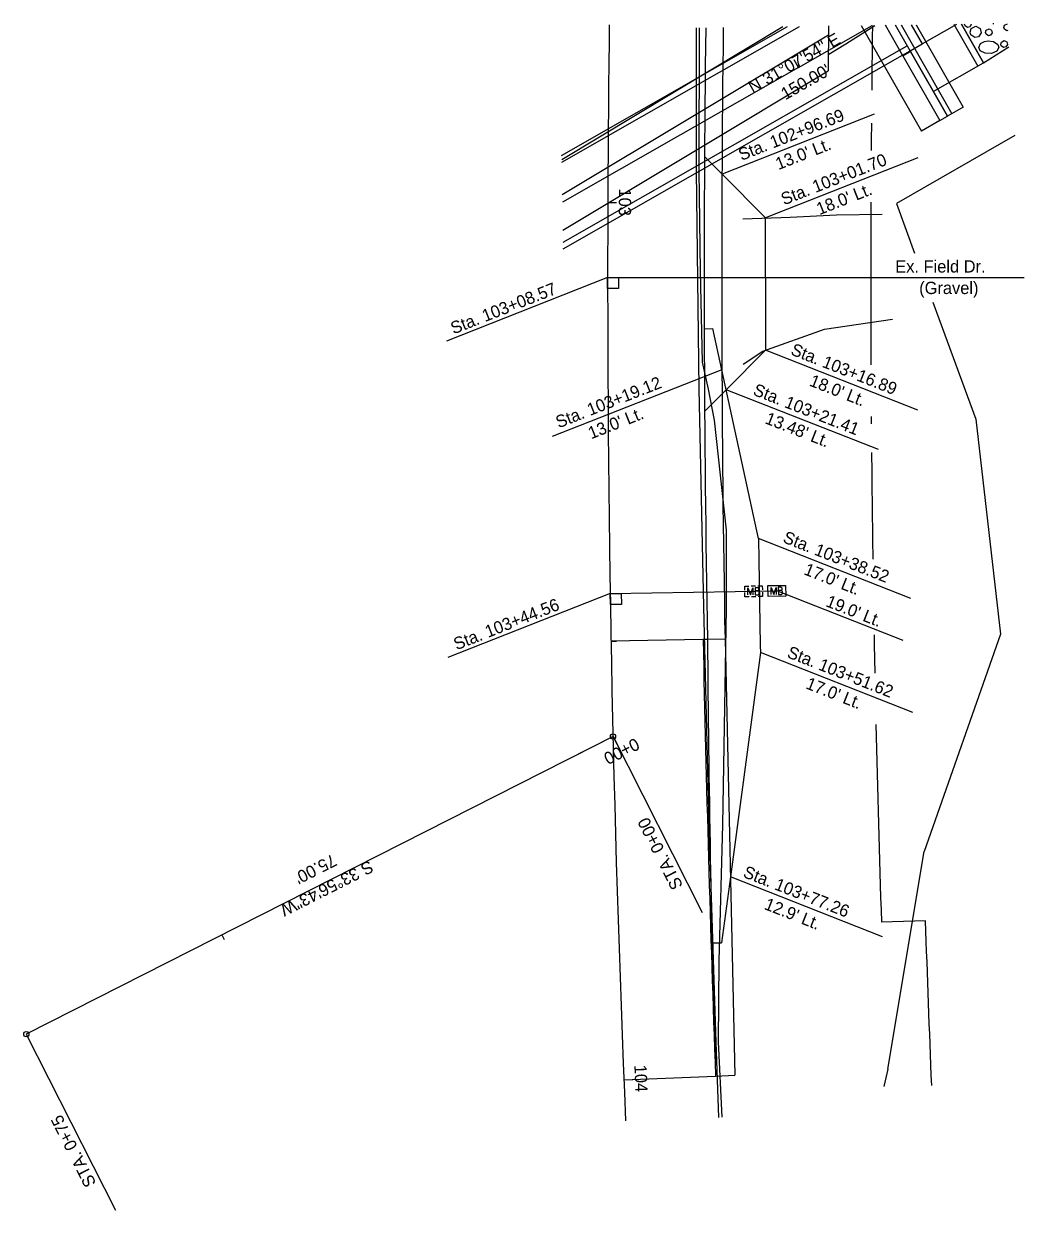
# Model space of a CAD drawing. Extents: x -189 to 370, y -316 to 69.
# Drawn here: x -189.4 to -75.3, y -65.9 to 69.3 of the extents above; entities that cross this region are included whole.
import ezdxf

# ---------------------------------------------------------------- set-up
doc = ezdxf.new("R2010")
doc.units = 0
for name, color, linetype in [('DR_P_Culvert', 7, 'Continuous'), ('DR_P_Erosion_Control', 7, 'Continuous'), ('DR_P_Paved_Gutter', 7, 'Continuous'), ('DR_X_Storm_Sewer', 7, 'Continuous'), ('DT_P_Slope_Break_Line', 7, 'Continuous'), ('GE_P_Alignment_100_Cardinal_Points', 7, 'Continuous'), ('GE_P_Alignment_100_Distances', 7, 'Continuous'), ('GE_P_Alignment_100_Stations', 7, 'Continuous'), ('GE_X_Alignment', 7, 'Continuous'), ('GE_X_Alignment_100_Stations', 7, 'Continuous'), ('HY_X_Water_Edge', 7, 'Continuous'), ('PF_P_Sta_Elev_Text', 7, 'Continuous'), ('PF_X_Text', 7, 'Continuous'), ('PV_P_Drive', 7, 'Continuous'), ('PV_P_Field_Drive', 7, 'Continuous'), ('PV_X_Driveway', 7, 'Continuous'), ('PV_X_EOP', 7, 'Continuous'), ('PV_X_Shoulder_Aggregate', 7, 'Continuous'), ('RD_X_Cells', 7, 'Continuous'), ('RW_P_Const_Limits', 7, 'Continuous'), ('RW_X_Esmt_SH', 7, 'Continuous'), ('ST_Text', 7, 'Continuous'), ('SV_X_Text', 7, 'Continuous'), ('TX_P_Misc', 7, 'Continuous'), ('XS_P_Finished_Grade', 7, 'Continuous')]:
    doc.layers.add(name, color=color, linetype=linetype)

msp = doc.modelspace()

# ---------------------------------------------------------------- linework, layer by layer
at = {"layer": 'DR_P_Culvert'}
for p, q in [((-128.04, 54.33), (-102.29, 69.02)), ((-128.03, 53.57), (-100.91, 69.04)), ((-127.86, 44.46), (-89.5, 66.34)), ((-89.5, 66.34), (-88.64, 66.84)), ((-89.17, 65.76), (-88.31, 66.26)), ((-127.85, 43.7), (-89.17, 65.76))]:
    msp.add_line(p, q, dxfattribs=at)
at = {"layer": 'DR_P_Erosion_Control'}
for p, q in [((-77.53, 69.17), (-77.22, 69.32)), ((-79.94, 64.88), (-77.04, 66.71))]:
    msp.add_line(p, q, dxfattribs=at)
for points in [[(-81.34, 69.31), (-81.33, 69.25), (-81.51, 68.98), (-81.77, 68.93), (-82.03, 69.11), (-82.09, 69.3)], [(-81.34, 68.8), (-80.82, 69.05), (-80.33, 68.82), (-80.19, 68.3), (-80.51, 67.85), (-80.93, 67.77), (-81.37, 68.07), (-81.47, 68.4), (-81.34, 68.8)], [(-78.76, 69.34), (-78.85, 69.33), (-78.87, 69.34)], [(-77.17, 68.58), (-77.29, 68.55), (-77.55, 68.73), (-77.61, 68.93), (-77.53, 69.17)], [(-79.63, 68.6), (-79.31, 68.75), (-79.02, 68.61), (-78.94, 68.3), (-79.13, 68.03), (-79.38, 67.98), (-79.65, 68.16), (-79.71, 68.36), (-79.63, 68.6)], [(-79.45, 67.39), (-78.78, 67.31), (-78.29, 66.98), (-78.18, 66.62), (-78.42, 66.21), (-79.04, 65.95), (-79.76, 65.98), (-80.3, 66.27), (-80.48, 66.65), (-80.27, 67.09), (-79.82, 67.33), (-79.42, 67.4)], [(-77.89, 67.26), (-77.57, 67.42), (-77.28, 67.28), (-77.2, 66.96), (-77.39, 66.7), (-77.64, 66.65), (-77.91, 66.82), (-77.97, 67.02), (-77.89, 67.26)]]:
    msp.add_lwpolyline(points, dxfattribs=at)
at = {"layer": 'DR_P_Paved_Gutter'}
for p, q in [((-86.93, 67.04), (-82.99, 69.29)), ((-82.46, 69.29), (-79.94, 64.89)), ((-85.66, 61.62), (-79.94, 64.89))]:
    msp.add_line(p, q, dxfattribs=at)
at = {"layer": 'DR_X_Storm_Sewer'}
for p, q in [((-128.03, 53.89), (-102.83, 69.01)), ((-97.6, 69.09), (-97.66, 63.96)), ((-97.61, 68.06), (-127.96, 49.85)), ((-127.89, 45.81), (-97.66, 63.96))]:
    msp.add_line(p, q, dxfattribs=at)
at = {"layer": 'DT_P_Slope_Break_Line'}
for p, q in [((-79.94, 64.88), (-82.46, 69.29)), ((-84.05, 58.8), (-88.26, 66.18))]:
    msp.add_line(p, q, dxfattribs=at)
at = {"layer": 'GE_P_Alignment_100_Cardinal_Points'}
for p, q in [((-122.18, -11.88), (-112, -31.94)), ((-122.18, -11.88), (-112, -31.94)), ((-189.07, -45.8), (-178.89, -65.87))]:
    msp.add_line(p, q, dxfattribs=at)
for centre in [(-122.18, -11.88), (-122.18, -11.88), (-189.07, -45.8)]:
    msp.add_circle(centre, 0.3, dxfattribs=at)
at = {"layer": 'GE_P_Alignment_100_Stations'}
for p, q in [((-101.04, 64.36), (-101.54, 65.23)), ((-122.18, -11.88), (-121.73, -12.77)), ((-122.18, -11.88), (-121.73, -12.77)), ((-166.77, -34.49), (-166.5, -35.03))]:
    msp.add_line(p, q, dxfattribs=at)
at = {"layer": 'GE_X_Alignment'}
for p, q in [((-101.04, 64.36), (-92.64, 69.15)), ((-101.04, 64.36), (-127.94, 49.01)), ((-122.18, -11.88), (-189.07, -45.8))]:
    msp.add_line(p, q, dxfattribs=at)
for start, end in [(179.26709, 179.78203), (179.78203, 182.44543)]:
    msp.add_arc((2128.84, 40.41), 2251.63, start, end, dxfattribs=at)
at = {"layer": 'GE_X_Alignment_100_Stations'}
for p, q in [((-122.77, 48.97), (-121.77, 48.97)), ((-122.77, 48.97), (-121.77, 48.97)), ((-122.4, -1.02), (-121.8, -1.01)), ((-122.4, -1.02), (-121.8, -1.01)), ((-120.93, -51), (-119.93, -50.96)), ((-120.93, -51), (-119.93, -50.96))]:
    msp.add_line(p, q, dxfattribs=at)
at = {"layer": 'HY_X_Water_Edge'}
msp.add_lwpolyline([(-97.58, 65.88), (-95.64, 67.07), (-92.31, 69.16)], dxfattribs=at)
at = {"layer": 'PF_P_Sta_Elev_Text'}
for p, q in [((-88.26, 66.18), (-88.31, 66.26)), ((-89.13, 65.69), (-89.17, 65.76))]:
    msp.add_line(p, q, dxfattribs=at)
msp.add_lwpolyline([(-89.17, 65.76), (-88.31, 66.26), (-88.26, 66.18), (-89.13, 65.69)], close=True, dxfattribs=at)
at = {"layer": 'PF_X_Text'}
for p, q in [((-93.88, 69.14), (-91.27, 64.56)), ((-89.17, 65.76), (-91.12, 69.17)), ((-88.31, 66.26), (-89.98, 69.19)), ((-89.31, 69.2), (-83.55, 59.09)), ((-88.17, 69.22), (-86.93, 67.04)), ((-87.6, 69.22), (-82.24, 59.83)), ((-83.32, 69.28), (-80.6, 64.51)), ((-88.31, 66.26), (-86.93, 67.04)), ((-89.13, 65.69), (-88.26, 66.18)), ((-89.13, 65.69), (-84.92, 58.31)), ((-88.26, 66.18), (-84.05, 58.8)), ((-91.27, 64.56), (-87.02, 57.11)), ((-82.24, 59.83), (-84.05, 58.8)), ((-84.92, 58.31), (-87.02, 57.11)), ((-84.92, 58.31), (-84.05, 58.8))]:
    msp.add_line(p, q, dxfattribs=at)
at = {"layer": 'PV_P_Drive'}
for p, q in [((-111.78, 34.59), (-110.78, 34.6)), ((-109.76, 29.91), (-110.78, 34.6)), ((-97.77, 34.58), (-97.78, 34.57)), ((-105.59, 10.68), (-109.76, 29.91)), ((-105.38, -2.31), (-108.8, -27.88)), ((-108.8, -27.88), (-109.81, -35.39)), ((-111.01, -35.41), (-109.81, -35.39))]:
    msp.add_line(p, q, dxfattribs=at)
msp.add_arc((2128.84, 40.41), 2234.63, 180.76225, 181.09547, dxfattribs=at)
at = {"layer": 'PV_P_Field_Drive'}
for p, q in [((-109.75, 52.22), (-111.74, 54.22)), ((-109.75, 52.22), (-104.79, 47.22)), ((-104.79, 40.41), (-104.79, 47.22)), ((-104.79, 40.41), (-104.79, 32.16)), ((-109.27, 27.64), (-104.79, 32.16)), ((-111.73, 25.16), (-109.27, 27.64))]:
    msp.add_line(p, q, dxfattribs=at)
at = {"layer": 'PV_X_Driveway'}
for points in [[(-107.37, 47.12), (-101.97, 47.32), (-96.68, 47.56), (-91.51, 47.64)], [(-107.35, 30.55), (-105.11, 32.04), (-98.05, 34.53), (-90.3, 35.66)]]:
    msp.add_lwpolyline(points, dxfattribs=at)
at = {"layer": 'PV_X_EOP'}
msp.add_lwpolyline([(-110.12, -55.28), (-110.43, -46.71), (-111.2, -21.94), (-111.81, 2.89), (-112.34, 27.73), (-112.65, 52.6), (-112.66, 68.88)], dxfattribs=at)
at = {"layer": 'PV_X_Shoulder_Aggregate'}
msp.add_lwpolyline([(-109.75, -55.26), (-110.14, -46.68), (-110.09, -37.44), (-109.65, -21.95), (-109.25, 2.7), (-109.24, 11.62), (-110.61, 24.17), (-111.29, 27.69), (-111.99, 30.79), (-112.2, 41.16), (-112.34, 52.6), (-112.31, 68.88)], dxfattribs=at)
at = {"layer": 'RD_X_Cells'}
for p, q in [((-106.42, 5.28), (-105.92, 5.29)), ((-106.39, 4.06), (-105.89, 4.07)), ((-106.15, 4.67), (-106.15, 4.67))]:
    msp.add_line(p, q, dxfattribs=at)
for points in [[(-107.15, 4.78), (-107.16, 5.26), (-106.68, 5.27)], [(-106.65, 4.05), (-107.14, 4.04), (-107.15, 4.53)], [(-106.79, 4.26), (-106.8, 5.06), (-106.5, 4.27), (-106.24, 5.07), (-106.22, 4.27)], [(-105.64, 4.72), (-105.61, 4.75), (-105.59, 4.77), (-105.58, 4.79), (-105.57, 4.8), (-105.56, 4.83), (-105.55, 4.84), (-105.54, 4.89), (-105.54, 4.91), (-105.54, 4.93), (-105.55, 4.97), (-105.56, 5), (-105.58, 5.03), (-105.61, 5.05), (-105.64, 5.06), (-105.65, 5.07), (-105.68, 5.08), (-105.99, 5.08), (-105.98, 4.28), (-105.63, 4.28), (-105.59, 4.31), (-105.55, 4.34), (-105.52, 4.39), (-105.5, 4.45), (-105.5, 4.5), (-105.5, 4.54), (-105.51, 4.58), (-105.54, 4.64), (-105.57, 4.67), (-105.64, 4.72), (-105.99, 4.71)], [(-105.66, 5.29), (-105.16, 5.3), (-105.15, 4.82)], [(-105.15, 4.57), (-105.14, 4.08), (-105.63, 4.07)]]:
    msp.add_lwpolyline(points, dxfattribs=at)
at = {"layer": 'RW_P_Const_Limits'}
for p, q in [((-76.37, 56.6), (-89.87, 48.85)), ((-89.87, 48.85), (-87.79, 43.21)), ((-85.73, 37.61), (-80.83, 24.28)), ((-80.83, 24.28), (-78.01, -0.21)), ((-78.01, -0.21), (-86.72, -24.98)), ((-90.84, -49.78), (-86.72, -24.98)), ((-90.84, -49.78), (-91.32, -51.78))]:
    msp.add_line(p, q, dxfattribs=at)
at = {"layer": 'RW_X_Esmt_SH'}
msp.add_line((-86.57, -32.88), (-91.57, -33.04), dxfattribs=at)
for radius, start, end in [(2221.63, 179.25863, 179.44925), (2221.63, 179.54618, 179.6263), (2221.63, 179.77784, 180.2566), (2221.63, 180.40789, 180.42928), (2221.63, 180.51414, 180.82718), (2221.63, 181.04939, 181.16289), (2221.63, 181.31337, 181.89467), (2216.63, 181.89467, 182.38005)]:
    msp.add_arc((2128.84, 40.41), radius, start, end, dxfattribs=at)
at = {"layer": 'ST_Text'}
for p, q in [((-92.39, 59.05), (-109.75, 52.22)), ((-87.42, 54.05), (-104.79, 47.22)), ((-122.79, 40.41), (-141.17, 33.17)), ((-87.42, 25.32), (-104.79, 32.16)), ((-109.76, 29.91), (-129.1, 22.3)), ((-91.9, 20.81), (-109.27, 27.64)), ((-88.22, 3.85), (-105.59, 10.68)), ((-122.5, 4.41), (-141.02, -2.88)), ((-89.11, -0.95), (-103.5, 4.71)), ((-88.01, -9.15), (-105.38, -2.31)), ((-91.44, -34.71), (-108.8, -27.88))]:
    msp.add_line(p, q, dxfattribs=at)
at = {"layer": 'SV_X_Text'}
msp.add_line((-103.5, 4.71), (-103.5, 4.71), dxfattribs=at)
msp.add_lwpolyline([(-104.51, 5.31), (-102.51, 5.34), (-102.49, 4.12), (-104.49, 4.09)], close=True, dxfattribs=at)
for points in [[(-104.14, 4.3), (-104.15, 5.1), (-103.85, 4.31), (-103.59, 5.11), (-103.57, 4.31)], [(-102.99, 4.76), (-102.96, 4.79), (-102.94, 4.81), (-102.93, 4.83), (-102.92, 4.84), (-102.91, 4.87), (-102.9, 4.89), (-102.89, 4.93), (-102.89, 4.95), (-102.89, 4.97), (-102.9, 5.01), (-102.91, 5.04), (-102.93, 5.07), (-102.96, 5.09), (-102.99, 5.1), (-103, 5.11), (-103.03, 5.12), (-103.34, 5.12), (-103.33, 4.32), (-102.98, 4.32), (-102.94, 4.35), (-102.9, 4.38), (-102.87, 4.43), (-102.85, 4.49), (-102.85, 4.55), (-102.85, 4.58), (-102.86, 4.62), (-102.89, 4.68), (-102.92, 4.71), (-102.99, 4.76), (-103.34, 4.75)]]:
    msp.add_lwpolyline(points, dxfattribs=at)
at = {"layer": 'TX_P_Misc'}
for p, q in [((-122.79, 40.41), (-75.29, 40.41)), ((-122.5, 4.41), (-103.5, 4.71)), ((-111.92, -0.83), (-122.4, -1.02)), ((-111.41, -0.82), (-111.92, -0.83)), ((-122.18, -11.88), (-126.81, -14.22)), ((-120.93, -51), (-110.49, -50.58))]:
    msp.add_line(p, q, dxfattribs=at)
for points in [[(-122.79, 40.41), (-121.54, 40.41), (-121.54, 39.16), (-122.79, 39.16)], [(-122.5, 4.41), (-121.25, 4.43), (-121.23, 3.18), (-122.48, 3.16)]]:
    msp.add_lwpolyline(points, close=True, dxfattribs=at)
for centre, radius, start, end in [((2128.84, 40.41), 2240.63, 179.27159, 181.05435), ((3163.7, 67.86), 3276.33, 181.20138, 182.07168), ((2104.62, 14.88), 2216.08, 180.406, 181.69265)]:
    msp.add_arc(centre, radius, start, end, dxfattribs=at)
at = {"layer": 'XS_P_Finished_Grade'}
for p, q in [((-109.41, -0.78), (-111.41, -0.82)), ((-109.41, -0.78), (-108.3, -50.49)), ((-110.49, -50.58), (-108.3, -50.49))]:
    msp.add_line(p, q, dxfattribs=at)
msp.add_arc((2128.84, 40.41), 2238.63, 179.27024, 181.05435, dxfattribs=at)

# ---------------------------------------------------------------- texts
at = {"layer": 'GE_P_Alignment_100_Cardinal_Points'}
for s, p in [('  STA. 0+00', (-113.7, -29.82)), ('  STA. 0+75', (-180.6, -63.72))]:
    msp.add_text(s, height=1.4, rotation=116.8922, dxfattribs=at).set_placement(p)
at = {"layer": 'GE_P_Alignment_100_Distances'}
for s, p in [("75.00'", (-154.15, -25.24)), ('S 33°56\'43"W', (-149.97, -25.95))]:
    msp.add_text(s, height=1.4, rotation=206.8922, dxfattribs=at).set_placement(p)
at = {"layer": 'GE_P_Alignment_100_Stations'}
for s, rotation, p in [('N 31°07\'54" E', 29.7057, (-106.25, 61.39)), ("150.00'", 29.7057, (-102.53, 60.61)), ('0+00', 206.8922, (-119.63, -11.99))]:
    msp.add_text(s, height=1.4, rotation=rotation, dxfattribs=at).set_placement(p)
at = {"layer": 'GE_X_Alignment_100_Stations'}
for s, rotation, p in [('103', 269.782, (-121.51, 50.57)), ('104', 272.3267, (-119.75, -49.31))]:
    msp.add_text(s, height=1.4, rotation=rotation, dxfattribs=at).set_placement(p)
at = {"layer": 'ST_Text'}
for s, rotation, p in [('Sta. 102+96.69', 21.4812, (-107.54, 53.71)), ("13.0' Lt.", 21.4812, (-103.32, 52.66)), ('Sta. 103+01.70', 21.4812, (-102.69, 48.64)), ("18.0' Lt.", 21.4812, (-98.65, 47.52)), ('Sta. 103+08.57', 21.4812, (-140.36, 33.93)), ('Sta. 103+16.89', 338.5188, (-102.02, 31.68)), ('Sta. 103+19.12', 21.4812, (-128.38, 23.23)), ("18.0' Lt.", 338.5188, (-99.89, 28.13)), ('Sta. 103+21.41', 338.5188, (-106.32, 27.09)), ("13.0' Lt.", 21.4812, (-124.68, 21.98)), ("13.48' Lt.", 338.5188, (-104.95, 23.84)), ('Sta. 103+38.52', 338.5188, (-102.91, 10.28)), ("17.0' Lt.", 338.5188, (-100.52, 6.63)), ("19.0' Lt.", 338.5188, (-98.02, 2.99)), ('Sta. 103+44.56', 21.4812, (-140.02, -2.06)), ('Sta. 103+51.62', 338.5188, (-102.44, -2.82)), ("17.0' Lt.", 338.5188, (-100.31, -6.37)), ('Sta. 103+77.26', 338.5188, (-107.45, -27.86)), ("12.9' Lt.", 338.5188, (-105.04, -31.52))]:
    msp.add_text(s, height=1.4, rotation=rotation, dxfattribs=at).set_placement(p)
for s, p in [('Ex. Field Dr.', (-90, 40.99)), ('(Gravel)', (-87.27, 38.54))]:
    msp.add_text(s, height=1.4, dxfattribs=at).set_placement(p)

doc.saveas('drawing.dxf')
